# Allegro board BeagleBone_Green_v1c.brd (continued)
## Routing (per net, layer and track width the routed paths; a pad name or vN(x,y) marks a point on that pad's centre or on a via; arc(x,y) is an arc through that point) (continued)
GND_EARTH: length 298
  TOP w0.889: MTG1.1 16.37,4.94 ; MTG1.1 16.37,1.41 ; MTG1.1 12.84,4.94 ; MTG1.1 12.84,1.41 ; MTG4.1 82.41,50.03 ; MTG4.1 78.88,50.03 ; MTG4.1 82.41,46.49 ; MTG4.1 78.88,46.49 ; 12.84,53.2 MTG3.1 ; MTG3.1 16.37,49.67 ; MTG3.1 16.37,53.2 ; MTG2.1 82.41,4.58 ; MTG2.1 78.88,4.58 ; MTG2.1 78.88,8.12 ; MTG2.1 82.41,8.12 ; 0.84,48.06 P4.9 0.84,46.64 ; 0.84,41.62 P4.8 0.84,40.2
  LYR2_GND w0.889: 12.84,53.2 MTG3.1 ; MTG3.1 16.37,53.2 ; MTG3.1 16.37,49.67 ; 78.88,46.49 MTG4.1 ; MTG4.1 78.88,50.03 ; MTG4.1 82.41,46.49 ; MTG4.1 82.41,50.03 ; MTG2.1 82.41,8.12 ; MTG2.1 78.88,8.12 ; MTG2.1 82.41,4.58 ; MTG2.1 78.88,4.58 ; 0.84,41.62 P4.8 0.84,40.2 ; 12.84,1.41 MTG1.1 ; MTG1.1 16.37,4.94 ; MTG1.1 12.84,4.94 ; MTG1.1 16.37,1.41 ; 0.84,46.64 P4.9 0.84,48.06
  LYR3 w0.889: 12.84,53.2 MTG3.1 ; MTG3.1 16.37,49.67 ; MTG3.1 16.37,53.2 ; 78.88,46.49 MTG4.1 ; MTG4.1 82.41,50.03 ; MTG4.1 78.88,50.03 ; MTG4.1 82.41,46.49 ; 0.84,46.64 P4.9 0.84,48.06 ; 0.84,40.2 P4.8 0.84,41.62 ; MTG1.1 16.37,1.41 ; MTG1.1 12.84,1.41 ; MTG1.1 16.37,4.94 ; MTG1.1 12.84,4.94 ; MTG2.1 82.41,4.58 ; MTG2.1 82.41,8.12 ; MTG2.1 78.88,8.12 ; MTG2.1 78.88,4.58
  LYR4 w0.889: 0.84,41.62 P4.8 0.84,40.2 ; MTG3.1 16.37,53.2 ; MTG3.1 16.37,49.67 ; MTG3.1 12.84,53.2 ; 78.88,46.49 MTG4.1 ; MTG4.1 82.41,46.49 ; MTG4.1 78.88,50.03 ; MTG4.1 82.41,50.03 ; 78.88,4.58 MTG2.1 ; MTG2.1 78.88,8.12 ; MTG2.1 82.41,8.12 ; MTG2.1 82.41,4.58 ; 12.84,1.41 MTG1.1 ; MTG1.1 16.37,1.41 ; MTG1.1 16.37,4.94 ; MTG1.1 12.84,4.94 ; 0.84,46.64 P4.9 0.84,48.06
  LYR4 w1.016: 11.3,21.97 7.71,18.38 P3.5 ; P3.6 v1(7.57,2.33)
  LYR5_PWR w0.889: 12.84,4.94 MTG1.1 ; MTG1.1 12.84,1.41 ; MTG1.1 16.37,1.41 ; MTG1.1 16.37,4.94 ; 0.84,41.62 P4.8 0.84,40.2 ; 0.84,48.06 P4.9 0.84,46.64 ; MTG4.1 82.41,46.49 ; MTG4.1 78.88,46.49 ; MTG4.1 78.88,50.03 ; MTG4.1 82.41,50.03 ; 12.84,53.2 MTG3.1 ; MTG3.1 16.37,49.67 ; MTG3.1 16.37,53.2 ; 78.88,8.12 MTG2.1 ; MTG2.1 82.41,4.58 ; MTG2.1 78.88,4.58 ; MTG2.1 82.41,8.12
  BOTTOM w0.381: P10.13 v1(84.96,43.94) ; v1(78.23,45.59) 77.61,44.97 P10.11 ; P4.7 4.55,39.3 ; 4.55,39.3 v1(3.89,38.63) ; 4.55,39.3 v1(5.24,38.61) ; 71.07,39.95 71.11,39.99 P10.15 72.34,41.14 72.36,41.17 ; v1(1.91,30.23) 2.86,30.23 R136.2 2.86,29.46 v1(1.91,29.46) ; P4.6 4.55,48.69 ; P10.14 v1(84.96,31.55) ; 9.4,26.29 9.02,26.67 C164.2 ; C166.2 7.87,26.42 ; 71.97,35.14 P10.16 ; P10.12 76.44,30.47
  BOTTOM w0.508: C165.2 C163.2 8.64,32.26 10.67,34.29 10.67,37.08 P5.13 ; 6.03,38.42 6.1,38.48
  BOTTOM w0.889: 74.05,30.47 P10.12 ; P10.12 75.26,29.82 ; P10.12 75.26,31.12 ; P4.9 2.77,46.64 ; P4.9 0.84,46.64 ; P4.9 0.84,48.06 ; 0.84,40.2 P4.8 ; P4.8 2.77,40.2 ; P4.8 0.84,41.62 ; P4.8 2.77,41.62 ; 78.88,8.12 MTG2.1 ; MTG2.1 82.41,8.12 ; MTG2.1 82.41,4.58 ; MTG2.1 78.88,4.58 ; MTG3.1 16.37,49.67 ; MTG3.1 12.84,53.2 ; MTG3.1 16.37,53.2 ; MTG1.1 16.37,1.41 ; MTG1.1 12.84,1.41 ; MTG1.1 16.37,4.94 ; MTG1.1 12.84,4.94 ; 73.96,44.32 P10.11 72.75,44.97 ; 78.88,46.49 MTG4.1 ; MTG4.1 82.41,46.49 ; MTG4.1 78.88,50.03 ; MTG4.1 82.41,50.03
  vias: v1(1.19,45.62) v1(1.45,49.99) v1(84.91,36.91) v1(84.89,32.18) v1(84.99,40.13)
GND_OSC0: length 9.4
  TOP w0.381: v2(44.2,39.62) 44.52,39.3 U5.V11
  BOTTOM w0.305: U17.4 48.09,40.04 48.13,40.01 ; R29.2 52.45,44.32 ; R29.2 51.05,44.32 ; R29.2 C25.2 ; R173.2 44.07,43.31
  BOTTOM w0.381: R174.2 43.05,38.99 ; R173.2 43.31,42.42
GND_OSC1: length 7.3
  TOP w0.254: U5.A5 49.32,22.18 50.04,21.46
  BOTTOM w0.381: v1(51.75,14.86) C22.1 ; C22.1 R30.2 ; C22.1 51.12,15.68 ; v1(49.91,14.99) 50.48,15.56 C21.1 51.12,15.68 ; 51.12,15.68 v1(51.12,17.78)
GNDA_ADC: length 46.4
  TOP w0.254: v1(47.32,25.21) U5.E8
  TOP w0.305: 46.12,21.97 U5.A9
  TOP w0.381: 46.12,21.97 46.12,21.95 46.48,21.59 46.48,17.91 45.85,17.27 C93.2 ; C93.2 v1(45.09,16.51) ; C93.2 C33.2 C31.2 C32.2
  LYR4 w0.381: v1(47.32,25.21) 46.29,25.21 45.85,24.77 45.85,23.24 46.48,22.61 46.48,20.32 45.09,18.92 v1(45.09,16.51) 45.18,16.51 47.83,13.86 47.83,11.1 49.76,9.17 51.23,9.17 51.56,8.84 53.01,8.84 53.95,7.9 53.95,7.39 56.52,4.82 56.52,4.19 57.34,3.37 59.25,3.37 P9.34
  BOTTOM w0.381: v1(45.09,16.51) 45.09,16.89 44.84,17.14 FB3.1
VBUS: length 4.9
  BOTTOM w0.629: P3.1 11.15,16.18 ; P3.1 9.42,16.18 ; P3.1 11.15,14.45 ; P3.1 9.42,14.45
VDD_1V8: length 35.5
  TOP w0.203: U2.40 23.86,18.83 23.82,18.87 23.82,19.36 24.27,19.81
  TOP w0.254: U5.E9 U5.D10 v1(44.92,25.21) ; v1(40.12,32.41) U5.N16 ; U5.R16 40.14,33.99 v1(40.08,33.99)
  TOP w0.381: 24.27,19.81 25.46,19.81 v1(26.92,18.35) v1(26.92,17.72)
  LYR3 w0.381: v1(26.92,17.72) v1(26.92,18.35)
  BOTTOM w0.305: v1(44.92,25.21) 45.61,24.52 C88.1 ; v1(40.08,33.99) 39.76,34.31 39.76,34.37 39.32,34.81 39.12,34.81 38.69,35.24 C86.1
  BOTTOM w0.381: C14.2 26.04,17.72 v1(26.92,17.72) v1(26.92,18.35) 26.04,18.35 C14.2 ; C14.2 25.4,18.35 25.4,19.43 24.51,20.32 20.07,20.32 18.54,18.8 17.4,18.8 ; FB1.1 33.78,32.13 33.02,32.89 v1(33.02,33.27) 33.4,33.27 C78.1 33.53,33.91 v1(33.02,33.91) ; v1(45.88,14.06) 45.1,14.06 v1(45.06,14.1) 45.06,14.12 45.09,14.15 45.09,14.99 45.34,15.24 FB2.2 46.35,14.44 45.97,14.06 v1(45.88,14.06)
VDD_3V3A: length 117.8
  TOP w0.203: v1(22.36,19.62) 22.36,19.11 22.66,18.81 U2.43
  TOP w0.254: U5.K14 v1(42.52,30.01) U5.L14 ; v1(40.91,34.02) U5.R15 ; U5.P8 U5.P7 v1(48.12,33.21) ; U5.N5 v1(49.72,31.61) ; U5.E13 v1(43.32,25.21) U5.E12 v1(44.12,25.21) U5.E11 v1(44.92,26.01) U5.E10 ; U5.J14 v1(41.72,28.41) U5.H14 ; U5.P10 v1(44.92,33.21) U5.P11 ; U5.P13 v1(42.52,33.21) ; U5.F14 v1(41.72,26.81) U5.G14 ; U5.P6 v1(48.92,33.21) ; v1(40.92,32.41) U5.N15 ; U5.P5 v1(49.72,33.21) ; U5.P12 v1(43.32,33.21)
  TOP w0.381: U3.5 39.67,45.75 v1(39.69,45.73) ; v1(53.09,45.85) R56.1 ; v1(22.66,40.08) 22.66,40.59 22.35,40.89 R169.2 ; v1(26.99,23.11) R4.1 ; R4.1 R3.1 ; R4.1 C37.1 ; C61.2 75.06,46.23 v1(75.56,45.72) ; R1.1 23.62,20.57 v1(24.38,21.34) ; v1(37.34,40.53) 37.49,40.53 37.72,40.77 C159.1 38.61,40.77 38.93,40.45 Y4.4 ; v1(55.6,46.61) C57.2
  LYR3 w0.381: v1(22.66,40.08) 22.66,39.85 23.19,39.32 34.57,39.32 35.36,38.53 v1(36.12,38.53) ; v1(22.36,19.62) 22.36,19.44 21.34,18.41 17.02,18.41 16.51,17.91 16.51,16.08 15.29,14.86 11.81,14.86 10.92,13.97 9.4,13.97 9.14,13.72 5.59,13.72 3.05,16.26 2.26,16.26 v1(1.7,16.81)
  BOTTOM w0.305: U17.8 45.73,42.15 45.47,42.42 R175.1 v2(45.09,43.31) ; v1(41.72,28.41) 41.72,27.72 C60.2 41.72,27.5 v1(41.72,26.81) 41.72,26.12 C70.2 ; C72.2 45.43,25.5 v1(44.92,26.01) ; v1(42.52,30.01) 42.63,30.12 C66.1 ; v1(44.92,33.21) 45.61,33.9 C56.2 ; v1(40.92,32.41) 39.92,31.41 39.81,31.41 39.14,30.73 C87.1
  BOTTOM w0.381: v1(22.66,40.08) 22.58,40.16 21.08,40.16 20.7,40.54 U4.1 ; R57.1 59.82,46.28 v1(60.27,45.82) 60.71,46.25 R58.1 ; C71.2 37.85,36.96 v1(37.97,36.83) ; v1(68.38,45.8) R66.1 R67.1 R68.1 R69.1 C61.2 R70.1 75.95,46.1 v1(75.56,45.72) ; R63.1 65.02,46.13 v1(64.62,45.72) 64.62,45.85 64.14,46.33 R62.1 ; C59.1 v1(43.5,20.95) ; C77.1 35.5,36.83 v1(36.08,36.83) ; C77.1 34.8,36.77 C67.1 ; C77.1 35.18,37.87 35.84,38.53 v1(36.12,38.53) ; v1(53.09,45.85) R56.1 R55.1 ; R171.1 49.4,39.88 49.19,40.09 49.15,40.09 48.98,40.26 v2(48.77,40.26) ; v1(49.72,31.61) 49.83,31.72 C73.2 ; R172.1 43.81,40.39 43.43,40.77 43.43,40.85 v2(43.35,40.94) ; R61.1 62.87,46.25 v1(62.46,45.85) 61.98,46.33 R60.1 ; R14.1 29.97,12.06 v1(30.23,12.32) ; 26.99,21.4 C152.1 R156.1 ; 26.99,21.4 27.43,20.95 U7.4 ; 26.99,21.4 v1(26.99,23.11) ; R65.1 67.18,46.28 v1(66.75,45.85) 66.29,46.3 R64.1 ; C38.1 C67.1 ; C67.1 v1(35.56,35.56) ; R52.1 2.26,16.26 v1(1.7,16.81) ; v1(22.36,19.62) 22.36,19.31 21.97,18.92 C15.2 ; v1(39.69,45.73) C158.1 ; R59.1 v1(55.6,46.61)
VDD_3V3AUX: length 19.4
  TOP w0.203: U2.1 19.58,17.44 19.2,17.82
  TOP w0.381: 19.2,17.82 19.2,19.81 19.3,19.91 C18.1 19.3,20.7 18.54,21.46 13.59,21.46 12.38,20.25 10.73,20.25 10.46,20.52 D1.2
VDD_3V3B: length 131.4
  TOP w0.203: U13.C6 31.71,42.66 31.6,42.55 v1(31.6,42.55) 31.2,42.55 U13.E6 ; U13.P5 25.37,43.16 v1(25.32,43.21) ; v1(28.06,40.82) 28.06,40.82 28.07,40.83 28.07,40.92 28.31,41.16 U13.K9 ; U13.J10 29.09,40.4 28.93,40.23 28.93,40.09 v1(28.92,40.08) ; v1(30.35,43.69) 30.6,43.45 U13.F5 ; v1(25.98,44.16) U13.P3 U13.N4 ; U13.M4 v1(28.07,43.66)
  TOP w0.254: v1(28.45,30.87) 28,30.87 U14.12
  TOP w0.381: C29.1 v1(34.29,9.84) 34.86,10.41 36.83,10.41 37.47,11.05 37.47,12.64 37.21,12.89 R23.1 36.83,14.1 ; R119.1 v1(31.75,33.66)
  TOP w0.635: J5.3 74.91,32.4 v2(74.24,33.07) ; J4.3 v2(78.55,17.54)
  LYR3 w0.381: v1(34.29,9.84) 39.43,9.84 39.62,9.66 41.05,9.66 41.45,10.06 46.2,10.06 46.91,9.35 55.07,9.35 55.37,9.65 v1(55.37,10.16)
  LYR4 w0.381: v1(55.37,10.16) 55.37,12.06 54.36,13.08 v1(54.36,14.24)
  LYR4 w0.635: v2(78.55,17.54) 78.55,24.76 v2(77.29,26.01) 74.24,29.06 v2(74.24,33.07) 74.24,38.43 v2(75.34,39.52)
  LYR5_PWR w0.889: 22.96,2.64 P9.3 21.49,2.64 ; 21.49,5.18 P9.4 ; P9.4 22.96,5.18 ; P9.4 22.96,3.71 ; P9.4 21.49,3.71
  BOTTOM w0.191: v1(28.45,30.87) 28.86,31.27 30.86,31.27 30.99,31.15 R112.2
  BOTTOM w0.254: v1(30.35,43.69) 30.55,43.49 30.55,43.13 30.48,43.06 C129.1 30.87,42.42 31.01,42.55 v1(31.6,42.55) ; U15.7 55.11,11.18 C155.2 55.13,10.68 U15.8 ; v1(28.06,40.82) 28.07,40.82 28.07,40.91 28.32,41.16 28.57,41.16 28.82,41.4 C128.1 29.21,40.76 29.09,40.64 29.09,40.4 28.93,40.23 28.93,40.09 v1(28.92,40.08) ; v1(25.32,43.21) 25.4,43.13 C127.1 ; C130.1 33.76,42.42 v1(33.71,42.47)
  BOTTOM w0.381: R106.1 v1(43.81,45.72) ; R11.1 18.16,38.1 18.54,38.48 v1(18.54,38.61) 18.54,38.73 18.92,39.12 C20.1 19.18,39.75 18.16,40.77 U4.3 ; R114.2 R112.2 ; R103.1 v1(26.04,45.72) ; R163.1 47.94,14.54 48.26,14.22 54.34,14.22 v1(54.36,14.24) ; R102.1 v1(46.35,45.72) ; v1(83.88,41.47) 83.7,41.65 P10.4 ; v1(28.45,30.87) 26.16,33.15 C135.1 ; R101.1 v1(48.9,45.72) ; R108.1 v1(24.77,45.72) ; R119.1 v1(31.75,33.66) ; C155.2 v1(55.37,10.16) ; R109.1 v1(42.55,45.72) ; P2.5 v1(34.29,9.84) ; R105.1 v1(47.62,45.72) ; R152.1 R153.1 R154.1 78.23,26.92 77.9,26.59 77.88,26.59 v2(77.29,26.01) ; R107.1 v1(23.5,45.72) ; R110.1 v1(45.09,45.72) ; R111.1 v1(29.21,48.26) ; C126.2 v1(23.5,43.94) ; R104.1 v1(27.3,45.72) ; v1(70.76,42.16) R157.2
  BOTTOM w0.762: P9.3 P9.4
  vias: v1(25.72,35.88) v1(79.5,40.89)
VDD_5V: length 7.1
  TOP w0.203: U2.10 18.92,13.84
  LYR4 w0.889: 24.03,5.18 P9.6 ; P9.6 25.5,3.71 ; P9.6 24.03,3.71 ; P9.6 25.5,5.18 ; 25.5,2.64 P9.5 24.03,2.64
  vias: v1(18.03,13.08) v1(18.03,12.37)
VDD_ADC: length 33.1
  TOP w0.254: v1(47.32,24.41) U5.D8
  TOP w0.381: v1(45.85,18.41) 45.72,18.29 C93.1 45.09,19.34 R27.1 45.84,20.09 45.84,20.95 v1(45.85,20.95)
  LYR3 w0.381: v1(47.32,24.41) 46.71,25.02 46.23,25.02 45.85,24.64 v1(45.85,20.95)
  LYR4 w0.381: v1(45.85,18.41) 45.85,17.17 48.39,14.63 48.39,11.3 49.96,9.73 53.09,9.73 54.08,8.74 55.65,8.74 57.15,7.24 57.15,5.08 P9.32
  BOTTOM w0.381: v1(45.85,18.41) 45.85,17.65 46.35,17.14 FB2.1
VDD_CORE: length 46.3
  TOP w0.254: U5.F6 v1(48.92,26.81) U5.G6 ; U5.F7 v1(48.12,26.01) ; U5.M13 v1(42.52,31.61) ; U5.K12 v1(44.12,30.01) ; v1(47.32,30.81) U5.L8 ; v1(46.52,30.81) U5.L9 ; U5.K8 v1(47.32,30.01) U5.L7 ; U5.L6 v1(48.92,30.01) U5.K6 ; U5.M11 v1(44.92,30.81) ; U5.H11 v1(44.12,27.61) ; U5.N13 v1(43.32,31.61) U5.N12 ; U5.J12 v1(43.32,28.41) ; U5.N8 v1(46.52,32.41) U5.N9 ; v1(48.12,26.81) U5.G7 ; U5.G10 v1(44.92,27.61)
  LYR4 w0.508: v1(28.57,13.08) v1(29.21,13.08) 31.11,14.99 31.11,18.8 30.73,19.18 30.73,22.17 32.13,23.57 v1(32.13,24.77) v1(32.13,25.4)
  BOTTOM w0.305: v1(46.52,30.81) 45.83,30.81 C47.1 45.61,30.81 v1(44.92,30.81) ; C45.1 38.86,29.84 39.83,30.81 v1(40.12,30.81) ; v1(44.12,30.01) 43.61,29.5 C46.1 43.61,28.7 v1(43.32,28.41) v1(44.12,27.61) ; C50.1 47.43,26.01 v1(48.12,26.01) v1(48.12,26.81) v1(48.92,26.81) ; v1(44.92,27.61) 45.03,27.5 C49.1 ; v1(46.52,32.41) 46.12,32.81 45.83,32.81 C42.1 ; v1(43.32,31.61) v1(42.52,31.61) 42.52,32.3 C41.1 ; v1(48.92,30.01) v1(47.32,30.01) U5.K8 46.92,29.32 C48.1 ; C43.1 v1(47.32,30.81)
  BOTTOM w0.381: v1(39.32,26.81) C54.1 C44.1 ; 28.57,13.78 L3.2 29.21,13.78 v1(29.21,13.08) v1(28.57,13.08) 28.57,13.78
  vias: v1(35.56,27.37) v1(35.56,26.61)
VDD_MPU: length 28.7
  TOP w0.254: U5.F10 45.25,26.48 44.59,26.48 U5.F11 U5.F12 v1(43.32,26.01) U5.F13 v1(42.52,26.81) U5.G13 42.81,27.32 42.81,27.9 U5.H13 v1(42.52,28.41) U5.J13
  TOP w0.635: 35.41,21.56 34.92,21.08 34.92,19.56 33.15,17.78 33.15,13.97 30.48,11.3 26.29,11.3
  BOTTOM w0.305: v1(43.32,26.01) 43.43,25.9 C63.1
  BOTTOM w0.381: v1(42.52,28.41) 42.63,28.52 C65.1 ; C62.2 35.18,21.84 35.43,22.1 v1(36.08,22.1) v1(36.08,21.46) 35.31,21.46 C62.2 ; C62.2 34.8,21.21 C64.1
  vias: v1(26.48,9.91) v1(27.11,9.91)
VDD_MPUON: length 10.6
  TOP w0.121: U5.A2 51.72,20.67 52.32,20.07 52.32,19.3 52.7,18.92 53.21,18.92 54.48,17.65 54.48,16.76 54.99,16.26 55.57,16.26 56.27,15.56 TP2.1
VDD_PHYA: length 6.9
  TOP w0.254: U14.27 22,31.87 21.78,32.08 21.78,32.26 21.27,32.77 v1(21.27,33.02) ; U14.1 23.33,28.28 v1(22.91,27.86)
  BOTTOM w0.381: R122.2 v1(18.73,31.11) ; R120.2 v1(18.73,29.21) ; R121.2 v1(18.73,30.16) ; R137.2 v1(10.67,29.21) ; R123.2 v1(18.73,32.07)
VDD_PLL: length 12.9
  TOP w0.254: v1(44.12,33.21) U5.R11 v1(44.92,34.01) 45.32,33.62 U5.R10 ; v1(48.12,25.21) U5.E7 ; U5.H15 v1(40.92,27.61)
  LYR3 w0.381: v1(38.52,31.61) 39.08,31.05 39.51,31.05 39.85,31.39 39.85,31.62 40.11,31.88 41.14,31.88 41.22,31.96 41.23,31.96 41.66,32.38 43.29,32.38 v1(44.12,33.21) v1(44.92,34.01)
  BOTTOM w0.305: C94.1 v1(44.12,33.21)
  BOTTOM w0.635: FB1.2 37.92,31.61 v1(38.52,31.61)
VDD_RTC: length 5.4
  TOP w0.254: v1(48.92,24.41) U5.D6
  BOTTOM w0.121: C104.1 48.75,20.66 48.75,22.29 49.32,22.86 49.32,23.54 49.32,24.01 v1(48.92,24.41)
VDDS: length 45.9
  TOP w0.254: U5.E6 v1(48.92,25.21) ; v1(46.52,33.21) U5.P9 ; v1(46.52,26.01) U5.F9 ; v1(43.32,30.01) U5.K13 ; U5.E14 v1(41.72,25.21) ; v1(41.72,33.21) U5.P14 ; U5.N6 v1(48.12,31.61)
  LYR5_PWR w0.305: v1(45.72,29.21) 45.47,29.46 43.87,29.46 v1(43.32,30.01)
  BOTTOM w0.121: 41.32,35.26 41.32,33.61
  BOTTOM w0.254: 41.32,33.61 v1(41.72,33.21)
  BOTTOM w0.305: 41.32,35.26 41.45,35.4 41.45,36.17 C80.1
  BOTTOM w0.381: 39.24,22.73 39.24,21.84 38.88,21.48 37.83,21.48 36.32,22.99 33.02,22.99 32.12,23.89 21.22,23.89 16.99,19.66 16.66,19.66 16.38,19.38 R9.1 R8.2 ; C80.1 41.64,36.3 41.91,36.58 41.91,37.73 42.13,37.95 45.35,37.95 46.35,36.94 46.35,36.79 46.61,36.54 46.65,36.54 46.76,36.43 46.76,36.3
VDDS_DDR: length 54.9
  TOP w0.254: v1(67.1,25.57) U12.H9 ; U5.L5 v1(49.72,30.01) U5.K5 ; v1(60.7,30.37) U12.B2 ; v1(59.9,19.16) U12.R1 ; v1(59.9,27.17) U12.F1 ; v1(67.1,20.76) U12.N9 ; v1(59.9,20.76) U12.N1 ; U5.E5 U5.F5 v1(49.72,26.81) U5.G5 ; U5.H5 v1(49.72,28.41) U5.J5 ; v1(66.3,23.16) U12.K8 ; v1(60.7,23.16) U12.K2 ; v1(59.9,29.57) U12.C1 ; v1(67.1,29.57) U12.C9 ; v1(67.1,27.97) U12.E9 ; v1(67.1,19.16) U12.R9 ; v1(66.3,31.17) U12.A8 ; v1(65.5,26.37) U12.G7 ; v1(59.9,31.17) U12.A1 ; v1(61.5,27.97) U12.D2 ; v1(67.1,28.77) U12.D9
  TOP w0.305: v1(60.7,25.57) U12.H2
  TOP w0.381: v1(22.61,7.24) 22.61,8.26 C9.2 23.24,8.13 v1(23.24,7.24) ; C96.2 v1(55.37,15.81)
  BOTTOM w0.305: C100.1 49.72,26.12 v1(49.72,26.81) 49.72,27.5 C99.1 49.72,27.72 v1(49.72,28.41) 49.72,29.1 C98.1 49.72,29.32 v1(49.72,30.01) 49.72,30.7 C97.1
  BOTTOM w0.381: v1(55.37,15.81) 55.24,15.68 C103.1 C102.1 ; v1(59.9,29.57) C108.1 ; C116.1 67.29,28.57 v1(67.1,28.77) ; v1(67.1,29.57) C115.1 ; v1(66.3,23.16) 67.5,24.36 C119.1 ; v1(60.7,25.57) 60.18,26.09 60.13,26.09 60.12,26.09 59.68,26.09 59.15,25.57 C110.1 ; v1(52.83,20.32) 52.2,20.32 C101.1 ; v1(52.83,20.32) 53.59,20.32 C95.2 53.59,19.56 v1(52.83,19.56) v1(52.83,20.32) ; R97.1 v1(64.01,18.36) ; v1(67.1,25.57) C117.1 67.97,25.67 67.97,26.52 68.33,26.87 C118.2 67.44,27.05 67.1,27.39 v1(67.1,27.97) ; v1(59.9,20.76) C112.1 ; C107.1 v1(59.9,31.17) ; v1(67.1,20.76) C120.1 ; R98.1 64.7,25.57 v1(65.5,26.37) ; C113.1 v1(59.9,19.16) ; C109.1 v1(59.9,27.17) ; C111.1 59.49,22.61 60.14,22.61 v1(60.7,23.16) ; C114.1 v1(66.3,31.17) ; v1(67.1,19.16) C121.1 ; C122.2 v1(66.04,16.83)
  vias: v1(18.85,6.99) v1(19.86,7.09) v1(49.91,5.97) v1(50.55,5.97) v1(53.72,5.97) v1(54.36,5.97) v1(57.91,5.97) v1(58.67,5.97) v1(59.44,5.97)
AIN0: length 38.3
  TOP w0.121: P9.39 66.67,3.17 66.67,4.95 65.41,6.22 62.61,6.22 59.18,9.65 48.26,9.65 47.86,10.05 47.86,19.79 48.51,20.45 48.51,21.77 48.12,22.16 48.12,22.81 U5.B6
AIN1: length 32
  TOP w0.121: v1(48.12,23.61) U5.C7
  LYR4 w0.133: v1(48.12,23.61) 48.51,23.22 48.51,22.48 50.42,20.57 51.18,20.57 52.6,19.15 54.76,19.15 57.53,16.38 57.53,10.77 62.2,6.1 66.29,6.1 P9.40
AIN2: length 36.8
  TOP w0.121: P9.37 64.26,3.05 64.26,5.08 63.63,5.71 62.1,5.71 58.67,9.14 47.75,9.14 47.36,9.53 47.36,20.06 48.01,20.7 48.01,21.51 47.32,22.2 47.32,22.81 U5.B7
AIN3: length 33.1
  TOP w0.121: U5.A7 47.72,22.18 48.27,21.63 48.27,20.58 47.61,19.93 47.61,9.79 48.01,9.4 58.93,9.4 62.36,5.97 63.88,5.97 P9.38
AIN4: length 31.1
  TOP w0.121: U5.C8 v1(47.32,23.61)
  LYR4 w0.133: v1(47.32,23.61) 48.13,22.8 48.13,21.34 49.28,20.19 51.16,20.19 52.53,18.82 53.19,18.82 53.34,18.67 54.8,18.67 57.15,16.32 57.15,10.46 61.59,6.02 61.59,3.17 P9.33
AIN5: length 32.4
  TOP w0.121: U5.B8 46.52,22.81 46.52,22.19 46.86,21.84 46.86,9.02 47.24,8.64 58.24,8.64 62.43,4.45 P9.36
AIN6: length 35.8
  TOP w0.121: U5.A8 46.92,22.17 47.75,21.34 47.75,20.83 47.12,20.19 47.12,9.27 47.5,8.89 58.42,8.89 61.85,5.46 63.37,5.46 63.88,4.95 63.88,2.92 P9.35
AIN7: length 10.4
  TOP w0.121: U5.C9 v1(46.52,23.61)
  LYR4 w0.133: v1(46.52,23.61) 47.75,22.38 47.75,18.41 48.17,18 48.23,18 v1(48.26,17.97)
  BOTTOM w0.121: v1(48.26,17.97) 48.26,17.91 47.94,17.59 R163.2 48.39,16.7 48.58,16.51 48.58,15.88 48.77,15.68 R164.1
B_UART0_RX: length 13.6
  TOP w0.121: R165.1 46.35,7.24 47.12,6.48 49.02,6.48 J1.4
  BOTTOM w0.121: U15.2 51.94,11.18 52.2,10.92 52.2,9.65 J1.4
B_UART0_TX: length 5.2
  BOTTOM w0.121: J1.5 52.7,8.64 52.45,8.89 52.45,11.18 51.95,11.68 U15.3
CAP_VBB_MPU: length 4.2
  TOP w0.121: U5.C10 44.93,23.62 v1(44.92,23.61)
  BOTTOM w0.121: C91.1 45.4,22.42 44.92,22.9 v1(44.92,23.61)
CAP_VDD_SRAM_CORE: length 5.2
  TOP w0.121: U5.D9 v1(46.52,24.41)
  BOTTOM w0.121: v1(46.52,24.41) 46.92,24.01 46.92,23.04 46.35,22.48 C89.1
CAP_VDD_SRAM_MPU: length 5
  TOP w0.121: v1(44.12,24.41) U5.D11
  BOTTOM w0.121: C90.1 44.52,20.26 44.52,24.01 v1(44.12,24.41)
CLKOUT2: length 55.5
  BOTTOM w0.121: P2.18 36,17.46 35.67,17.8 35.67,19.98 36.28,20.59 39.9,20.59 40.13,20.83 40.89,20.83 41.08,20.64 41.08,19.68 R19.2 R20.1 42.55,18.54 41.59,17.59 41.59,14.95 42.89,13.65 46.7,13.65 46.89,13.84 60,13.84 67.36,6.48 69.98,6.48 71.63,4.83 71.63,3.05 P9.41
CLKOUT_SRC: length 5.1
  TOP w0.121: U5.D14 v1(41.72,24.41)
  BOTTOM w0.121: R19.1 41.59,22.99 41.32,23.26 41.32,24.01 v1(41.72,24.41)
CRS: length 2.7
  TOP w0.121: U14.14 28.55,31.87 28.92,32.24 29.51,32.24 R139.2
DDR_A0: length 23.9
  TOP w0.121: v1(61.5,20.76) U12.N3 ; U5.F3 v1(51.32,26.01)
  LYR3 w0.133: v1(53.85,23.11) 53.34,23.11 53.21,22.99 53.21,21.21 54.86,19.56 54.86,19.3 57.02,17.14 61.59,17.14 62.36,17.91 62.36,20.7 61.98,21.08 61.82,21.08 v1(61.5,20.76)
  BOTTOM w0.121: v1(51.32,26.01) 51.73,26.42 52.32,26.42 52.58,26.16 52.58,24.38 v1(53.85,23.11)
DDR_A1: length 24.1
  TOP w0.121: v1(58.93,23.88) 58.93,24.77 57.72,25.97 56.58,25.97 54.54,28.01 U5.H1 ; v1(65.5,19.96) U12.P7
  LYR3 w0.121: 60.2,23.87 60.5,23.57 61.67,23.57
  LYR3 w0.133: 61.67,23.57 61.78,23.57 62.23,23.11 62.61,23.11 63.88,21.84 63.88,20.83 63.5,20.45 63.5,18.9 63.63,18.77 64.39,18.77 64.52,18.9 64.52,19.05 64.39,19.18 64.01,19.18 63.88,19.3 63.88,20.19 64.01,20.32 64.14,20.32 64.26,20.19 64.26,19.68 64.39,19.56 64.64,19.56 64.77,19.68 64.77,20.19 64.9,20.32 65.14,20.32 v1(65.5,19.96) ; 60.2,23.87 58.93,23.87 v1(58.93,23.88)
DDR_A2: length 23.9
  TOP w0.121: v1(61.5,19.96) U12.P3 ; U5.E4 v1(50.52,25.21)
  LYR3 w0.121: v1(61.5,19.96) 61.1,20.36 61.1,22.09
  LYR3 w0.133: 61.1,22.09 60.83,22.35 59.44,22.35 59.05,21.97 56.77,21.97 56.64,22.1 56.64,23.5 56.77,23.62 57.4,23.62 57.51,23.72 57.51,24.16 57.4,24.26 56.77,24.26 56.64,24.38 56.64,25.4 54.72,27.32 54.5,27.32 54.26,27.08 54.26,26.9 55.12,26.04 55.12,25.15 54.36,24.38 51.12,24.38 50.52,24.98 v1(50.52,25.21)
DDR_A3: length 24
  TOP w0.121: v1(51.32,23.61) U5.C3 ; v1(60.7,20.76) U12.N2
  LYR3 w0.121: v1(60.7,20.76) 60.3,21.16 59.61,21.16
  LYR3 w0.133: v1(51.32,23.61) 52.2,23.61 52.32,23.48 52.32,22.35 52.45,22.23 52.7,22.23 52.83,22.35 52.83,23.48 52.96,23.61 55.04,23.61 55.12,23.53 55.12,23.32 55.04,23.24 54.37,23.24 54.29,23.16 54.29,22.94 54.37,22.86 55.04,22.86 55.12,22.78 55.12,22.56 55.04,22.48 54.37,22.48 54.29,22.4 54.29,22.2 54.37,22.12 54.53,22.12 54.61,22.05 54.61,21.67 54.69,21.59 54.91,21.59 54.99,21.67 54.99,22.05 55.07,22.12 55.42,22.12 55.5,22.2 55.5,24.43 55.58,24.51 55.8,24.51 55.88,24.43 55.88,21.34 56.01,21.21 59.56,21.21 59.61,21.16
DDR_A4: length 23.9
  TOP w0.121: v1(56.13,16.26) 56.52,16.64 56.52,17.02 53.72,19.81 53.72,20.57 52.96,21.34 52.96,22.53 52.68,22.81 52.36,22.81 52.12,23.05 52.12,23.61 U5.C2 ; v1(66.3,19.96) U12.P8
  LYR3 w0.121: 65.28,19.56 65.9,19.56 v1(66.3,19.96)
  LYR3 w0.133: v1(56.13,16.26) 56.39,16 62.36,16 63.12,16.76 64.77,16.76 65.02,17.02 65.02,19.3 65.28,19.56
DDR_A5: length 23.9
  TOP w0.121: U5.B1 52.74,23.21 53.34,22.61 53.34,22.23 53.47,22.1 v1(53.85,22.1) ; v1(60.7,19.96) U12.P2
  LYR3 w0.121: v1(60.7,19.96) 61.1,19.56 61.1,18.17 61.09,18.16
  LYR3 w0.133: 61.09,18.16 60.83,17.91 59.44,17.91 59.31,18.03 59.31,20.7 59.18,20.83 57.78,20.83 57.66,20.7 57.66,18.41 57.53,18.29 56.9,18.29 56.64,18.54 56.64,20.7 56.52,20.83 56.26,20.83 56.13,20.7 56.13,19.68 56.01,19.56 55.75,19.56 55.63,19.68 55.63,21.64 55.55,21.72 55.32,21.72 55.24,21.64 55.24,21.03 55.17,20.95 54.54,20.95 54.29,21.2 54.29,21.65 v1(53.85,22.1)
DDR_A6: length 24.1
  TOP w0.121: v1(66.3,19.16) U12.R8 ; v1(49.72,24.41) U5.D5
  BOTTOM w0.121: v1(49.72,24.41) 50.12,24.81 51.39,24.81 53.59,22.61 53.98,22.61 55.37,21.21 55.37,18.67 57.28,16.76 64.52,16.76 65.9,18.15 65.9,18.76 v1(66.3,19.16)
DDR_A7: length 24.1
  TOP w0.121: v1(60.7,19.16) U12.R2 ; v1(57.15,19.91) 57.63,19.43 58.17,19.43 58.29,19.3 58.29,18.03 58.17,17.91 57.4,17.91 55.63,19.68 55.63,23.88 54.36,25.15 54.36,25.78 54.13,26.01 52.12,26.01 U5.E2
  BOTTOM w0.121: v1(57.15,19.91) 59.16,19.91 59.61,20.36 62.23,20.36 62.36,20.24 62.36,19.69 62.23,19.56 U12.R2 v1(60.7,19.16)
DDR_A8: length 23.9
  TOP w0.121: v1(66.3,18.36) U12.T8 ; v1(50.52,24.41) U5.D4
  BOTTOM w0.121: v1(66.3,18.36) 66.3,18.04 64.64,16.38 57.15,16.38 54.99,18.54 54.99,20.68 54.61,21.06 52.19,21.06 51.94,21.31 51.94,23.75 51.28,24.41 v1(50.52,24.41)
DDR_A9: length 24
  TOP w0.121: v1(53.85,21.46) 53.85,20.95 53.97,20.83 54.13,20.83 54.25,20.95 54.25,22.46 54.1,22.61 53.79,22.61 53.09,23.31 53.09,23.44 U5.C1 ; v1(61.5,19.16) U12.R3
  LYR3 w0.133: v1(61.5,19.16) 61.5,19.43 61.63,19.56 61.85,19.56 61.98,19.43 61.98,18.03 61.47,17.53 58.93,17.53 58.8,17.65 58.8,20.32 58.67,20.45 58.29,20.45 58.17,20.32 58.17,17.65 58.04,17.53 57.15,17.53 55.24,19.43 55.24,20.32 54.99,20.57 54.36,20.57 53.85,21.08 v1(53.85,21.46)
DDR_A10: length 24
  TOP w0.121: v1(65.5,22.36) U12.L7 ; U5.F4 v1(50.52,26.01)
  LYR3 w0.121: 51.68,26.41 50.92,26.41 v1(50.52,26.01)
  LYR3 w0.133: 51.68,26.41 52.2,26.92 52.2,28.32 52.58,28.71 55.75,28.71 56.83,27.62 57.72,27.62 59.31,26.04 62.36,26.04 64.39,24 65.66,24 65.79,23.88 65.79,23.62 65.66,23.5 64.77,23.5 64.64,23.37 64.64,23.11 64.77,22.99 65.66,22.99 65.79,22.86 65.79,22.65 v1(65.5,22.36)
DDR_A11: length 23.9
  TOP w0.121: v1(65.5,19.16) U12.R7 ; v1(53.85,26.81) 52.12,26.81 U5.F2
  BOTTOM w0.121: v1(65.5,19.16) 65.02,19.16 64.77,18.91 64.77,18.16 64.14,17.53 57.53,17.53 56.13,18.92 56.13,23.24 55.88,23.5 54.61,23.5 53.34,24.77 53.34,26.3 v1(53.85,26.81)
DDR_A12: length 24.1
  TOP w0.121: v1(65.5,20.76) U12.N7 ; v1(51.32,25.21) U5.E3
  LYR3 w0.133: v1(51.32,25.21) 51.38,25.15 54.1,25.15 54.36,25.4 54.36,25.78 54.1,26.04 53.21,26.04 52.96,26.29 52.96,27.69 53.21,27.94 55.12,27.94 56.64,26.42 57.91,26.42 59.56,24.77 61.22,24.77 61.47,25.02 62.23,25.02 63.88,23.37 63.88,22.38 v1(65.5,20.76)
DDR_A13: length 24
  TOP w0.121: U5.H3 v1(51.32,27.61) ; v1(61.5,18.36) U12.T3
  BOTTOM w0.121: v1(51.32,27.61) 53.92,27.61 54.36,27.18 54.36,24.26 54.74,23.88 56.26,23.88 56.52,23.62 56.52,19.05 57.66,17.91 63.37,17.91 63.5,18.03 63.5,18.24 63.37,18.36 v1(61.5,18.36)
DDR_A14: length 24
  TOP w0.121: v1(50.52,27.61) U5.H4 ; v1(65.5,18.36) U12.T7
  BOTTOM w0.121: v1(50.52,27.61) 50.52,27.58 50.9,27.21 52.55,27.21 52.96,26.8 52.96,24.64 55.75,21.84 55.75,18.8 57.4,17.14 64.28,17.14 v1(65.5,18.36)
DDR_A15: length 24
  TOP w0.121: U12.M7 64.52,21.38 64.52,18.11 63.07,16.66 57.35,16.66 54.61,19.41 54.61,23.37 53.57,24.41 51.32,24.41 U5.D3
DDR_BA0: length 24.1
  TOP w0.121: v1(60.7,21.56) U12.M2 ; U5.C4 v1(50.52,23.61)
  LYR3 w0.121: 50.12,22.48 50.12,23.48 50.25,23.61 v1(50.52,23.61) ; 50.92,23.74 50.92,22.48
  LYR3 w0.133: 50.92,22.48 51.05,22.35 51.44,22.35 51.56,22.23 51.56,21.46 51.44,21.34 51.18,21.34 51.05,21.46 51.05,21.84 50.93,21.97 50.67,21.97 50.55,21.84 50.55,21.46 50.42,21.34 50.25,21.34 50.12,21.46 50.12,22.48 ; 50.92,23.74 50.92,23.89 51.05,24.02 54.5,24.02 55.5,25.02 55.5,25.65 55.6,25.75 55.78,25.75 56.26,25.27 56.26,21.97 56.64,21.59 59.18,21.59 59.56,21.97 60.57,21.97 60.7,21.84 v1(60.7,21.56)
DDR_BA1: length 24.1
  TOP w0.121: v1(66.3,20.76) U12.N8 ; U5.E1 v1(53.85,25.61)
  LYR3 w0.133: v1(53.85,25.61) 52.62,25.61 52.32,25.91 52.32,26.29 52.58,26.54 52.58,28.07 52.83,28.32 55.37,28.32 56.93,26.76 58.08,26.76 59.69,25.15 61.09,25.15 61.21,25.27 61.21,25.53 61.34,25.65 62.1,25.65 64.23,23.52 64.23,22.63 65.05,21.82 65.66,21.82 65.82,21.65 65.82,21.24 v1(66.3,20.76)
DDR_BA2: length 24.1
  TOP w0.121: v1(61.5,21.56) U12.M3 ; v1(51.32,22.81) U5.B3
  LYR3 w0.133: v1(61.5,21.56) 61.98,21.56 62.1,21.69 62.1,22.1 62.23,22.23 62.48,22.23 62.74,21.97 62.74,21.59 62.48,21.34 62.48,21.08 62.74,20.83 62.74,17.53 61.98,16.76 56.9,16.76 54.48,19.18 54.48,19.43 52.7,21.21 52.51,21.21 52.39,21.08 52.39,20.83 52.26,20.7 52.07,20.7 51.94,20.83 51.94,22.99 51.82,23.11 51.63,23.11 v1(51.32,22.81)
DDR_CASN: length 24
  TOP w0.121: U5.F1 54.48,26.41 54.74,26.16 54.74,25.4 55.37,24.77 55.88,24.77 56.01,24.64 56.01,19.81 56.13,19.68 56.52,19.68 56.64,19.81 56.64,21.21 56.77,21.34 57.42,21.34 57.55,21.21 57.55,19.94 57.68,19.81 58.17,19.81 58.29,19.94 58.29,20.19 58.17,20.32 58.04,20.32 57.91,20.45 57.91,20.7 58.04,20.83 58.17,20.83 58.29,20.95 58.29,21.46 58.17,21.59 57.28,21.59 57.15,21.72 v1(57.15,22.48) ; v1(61.5,23.16) U12.K3
  LYR3 w0.133: v1(57.15,22.48) 59.05,22.48 59.31,22.73 61.07,22.73 v1(61.5,23.16)
DDR_CKE: length 25.1
  TOP w0.121: v1(67.1,23.16) U12.K9 ; U5.G3 v1(51.32,26.81)
  LYR3 w0.133: v1(51.32,26.81) 51.82,27.3 51.82,28.83 51.69,28.96 51.18,28.96 51.05,29.08 51.05,29.34 51.18,29.46 52.83,29.46 53.21,29.08 55.88,29.08 57.02,27.94 57.91,27.94 59.44,26.42 62.61,26.42 64.64,24.38 67.18,24.38 67.31,24.26 67.31,23.37 v1(67.1,23.16)
  BOTTOM w0.121: R96.2 v1(67.1,23.16)
DDR_CLK: length 24
  TOP w0.095: U12.J7 64.94,24.2 64.74,24.2 63.75,23.22 63.75,19.7 61.58,17.53 57.42,17.53 55.27,19.67 55.27,23.72 53.8,25.2 52.36,25.2 51.98,24.81 U5.D2
DDR_CLKN: length 24
  TOP w0.095: U12.K7 65.37,23.56 65.48,23.67 65.48,23.82 65.37,23.92 64.85,23.92 64.03,23.1 64.03,19.58 61.7,17.25 57.3,17.25 54.99,19.56 54.99,23.61 53.68,24.92 52.63,24.92 U5.D1
DDR_CSN: length 23.9
  TOP w0.121: U5.H2 52.12,28.41 54.65,28.41 56.71,26.35 57.85,26.35 59.44,24.77 59.44,23.44 59.36,23.37 58.88,23.37 58.8,23.29 58.8,22.09 59.05,21.84 59.05,18.41 59.18,18.29 59.31,18.29 59.44,18.41 59.44,21.97 59.18,22.23 59.18,22.78 59.26,22.86 59.49,22.86 59.56,22.78 59.56,22.44 59.64,22.36 60.7,22.36 U12.L2
DDR_D0: length 23.3
  TOP w0.121: v1(51.32,31.61) U5.M3 ; v1(62.3,27.97) U12.E3
  LYR3 w0.133: v1(51.32,31.61) 51.68,31.61 52.96,32.89 60.45,32.89 63.75,29.59 63.75,27.43 63.63,27.3 63.12,27.3 62.99,27.43 62.99,29.72 62.87,29.84 62.43,29.84 62.3,29.72 v1(62.3,27.97)
DDR_D1: length 23.3
  TOP w0.121: v1(65.5,27.17) U12.F7 ; v1(50.52,31.61) U5.M4
  LYR3 w0.121: v1(65.5,27.17) 65.9,26.77 66.47,26.77 66.7,26.53 66.7,25.74 66.7,25.39 66.47,25.16 ; v1(50.52,31.61) 50.92,31.21 50.92,30.64 51.16,30.41 52.78,30.41
  LYR3 w0.133: 66.47,25.16 66.08,24.77 64.89,24.77 62.9,26.76 59.6,26.76 57.4,28.96 56.77,28.96 56.26,29.46 53.72,29.46 52.78,30.41
DDR_D2: length 23.3
  TOP w0.121: U5.N1 55.49,32.01 55.88,31.62 57.02,31.62 57.15,31.75 57.15,32.64 57.02,32.77 54.86,32.77 54.74,32.89 54.74,33.15 54.86,33.27 61.09,33.27 61.21,33.15 61.21,32.13 62.73,30.61 62.73,27.43 62.47,27.17 61.98,27.17 61.98,27.17 61.5,27.17 U12.F2
DDR_D3: length 23.3
  TOP w0.121: U5.N2 52.12,32.41 55.86,32.41 v1(56.13,32.13) ; v1(66.3,27.17) U12.F8
  BOTTOM w0.121: v1(56.13,32.13) 60.83,32.13 62.36,30.61 62.36,29.08 63.18,28.26 63.18,27.69 63.31,27.56 63.5,27.56 63.63,27.69 63.63,28.57 63.75,28.7 64.01,28.7 64.14,28.57 64.14,27.69 64.26,27.56 64.52,27.56 64.64,27.69 64.64,28.57 64.77,28.7 65.58,28.7 65.91,28.37 66.5,28.37 66.7,28.17 66.7,27.57 v1(66.3,27.17)
DDR_D4: length 23.3
  TOP w0.121: U12.H3 63.52,25.17 64.26,25.91 64.26,31.75 63.37,32.64 v1(62.36,32.64) ; U5.N3 v1(51.32,32.41)
  LYR3 w0.133: v1(51.32,32.41) 51.33,32.41 52.58,33.66 61.34,33.66 v1(62.36,32.64)
DDR_D5: length 23.3
  TOP w0.121: U5.N4 v1(50.52,32.41) ; v1(66.3,25.57) U12.H8
  LYR3 w0.121: v1(50.52,32.41) 50.92,32.01 51.57,32.01
  LYR3 w0.133: v1(66.3,25.57) 65.88,25.15 65.15,25.15 64.26,26.04 64.26,29.72 60.71,33.27 52.83,33.27 51.57,32.01
DDR_D6: length 23.3
  TOP w0.121: U12.G2 61.5,25.56 63.41,25.56 63.88,26.04 63.88,31.24 v1(62.99,32.13) ; U5.P3 v1(51.32,33.21)
  LYR3 w0.133: v1(62.99,32.13) 62.99,32.64 61.59,34.04 52.45,34.04 51.63,33.21 v1(51.32,33.21)
DDR_D7: length 23.3
  TOP w0.121: v1(65.5,25.57) U12.H7 ; U5.P4 v1(50.52,33.21)
  LYR3 w0.121: 51.62,33.61 50.92,33.61 v1(50.52,33.21)
  LYR3 w0.133: 51.62,33.61 52.4,34.39 61.87,34.39 64.77,31.5 64.77,26.3 v1(65.5,25.57)
DDR_D8: length 20.3
  TOP w0.121: U5.J1 54.76,28.81 56.83,26.73 58.86,26.73 59.37,26.23 59.37,25.34 59.94,24.77 62.23,24.77 62.36,24.64 62.36,23.24 62.48,23.11 62.99,23.11 64.64,24.77 64.64,27.91 U12.D7
DDR_D9: length 20.3
  TOP w0.121: U5.K1 55.77,29.61 v1(56.13,29.97) ; v1(61.5,29.57) U12.C3
  LYR3 w0.133: v1(56.13,29.97) 56.52,29.97 56.64,30.1 56.64,32 56.77,32.13 57.53,32.13 57.66,32 57.66,29.84 57.78,29.72 58.29,29.72 58.42,29.84 58.42,32 58.55,32.13 59.05,32.13 59.18,32 59.18,28.83 59.31,28.7 61.37,28.7 61.5,28.83 v1(61.5,29.57)
DDR_D10: length 20.3
  TOP w0.121: v1(66.3,29.57) U12.C8 ; U5.K2 52.12,30.01 v1(53.85,30.01)
  BOTTOM w0.121: v1(66.3,29.57) 65.82,29.08 62.99,29.08 62.74,29.34 62.74,30.73 60.83,32.64 55.75,32.64 55.24,32.13 55.24,29.97 55.12,29.84 54.48,29.84 54.32,30.01 v1(53.85,30.01)
DDR_D11: length 20.1
  TOP w0.121: v1(60.7,29.57) U12.C2 ; v1(51.32,30.01) U5.K3
  BOTTOM w0.121: v1(60.7,29.57) 61,29.27 61,29.08 60.88,28.96 58.17,28.96 58.04,28.83 58.04,28.57 58.17,28.45 60.12,28.45 60.24,28.33 60.24,27.93 60.07,27.76 57.81,27.76 57.56,28.02 57.56,28.84 57.44,28.96 55.75,28.96 55.24,29.46 53.59,29.46 53.42,29.64 53.42,30.21 53.3,30.33 53.06,30.33 52.96,30.23 52.96,29.59 52.83,29.46 51.22,29.46 51.1,29.58 51.1,29.79 v1(51.32,30.01)
DDR_D12: length 20.2
  TOP w0.121: v1(65.5,31.17) U12.A7 ; U5.K4 v1(50.52,30.01)
  BOTTOM w0.121: v1(65.5,31.17) 65.5,31.53 63.31,33.72 54.55,33.72 52.58,31.75 52.58,30.16 52.45,30.04 52.2,30.04 52.07,30.16 52.07,30.28 51.94,30.41 50.92,30.41 v1(50.52,30.01)
DDR_D13: length 20.2
  TOP w0.121: v1(60.7,31.17) U12.A2 ; v1(51.32,30.81) U5.L3
  LYR3 w0.133: v1(60.7,31.17) 60.71,31.17 60.71,32 60.17,32.54 53.21,32.54 53.09,32.41 53.09,32 53.21,31.88 55.5,31.88 55.63,31.75 55.63,30.1 55.5,29.97 54.48,29.97 54.36,30.1 54.36,31.11 54.23,31.24 52.07,31.24 51.64,30.81 v1(51.32,30.81)
DDR_D14: length 20.3
  TOP w0.121: v1(66.3,30.37) U12.B8 ; U5.L4 v1(50.52,30.81)
  BOTTOM w0.121: v1(66.3,30.37) 65.9,30.77 65.9,31.64 63.5,34.04 54.36,34.04 51.53,31.21 50.92,31.21 v1(50.52,30.81)
DDR_D15: length 20.1
  TOP w0.121: U5.M1 53.34,31.21 54.86,31.21 54.99,31.08 54.99,30.86 54.86,30.73 54.48,30.73 54.36,30.61 54.36,30.23 54.48,30.1 55.5,30.1 55.63,30.23 55.63,30.48 55.75,30.61 59.31,30.61 59.44,30.73 59.44,30.99 59.31,31.11 58.04,31.11 57.91,31.24 57.91,31.5 58.04,31.62 59.31,31.62 59.44,31.75 59.44,32 59.31,32.13 58.04,32.13 57.91,32.26 57.91,32.51 58.04,32.64 60.03,32.64 U12.A3
DDR_DQM0: length 23.3
  TOP w0.121: v1(65.5,27.97) U12.E7 ; U5.M2 52.12,31.61 55.26,31.61 55.7,31.17 v1(56.13,31.17)
  BOTTOM w0.121: v1(65.5,27.97) 65.15,27.97 65.02,27.84 65.02,27.3 64.9,27.18 62.87,27.18 62.74,27.3 62.74,28.19 61.98,28.96 61.98,30.48 60.71,31.75 56.77,31.75 56.64,31.62 56.64,29.59 56.52,29.46 55.75,29.46 55.63,29.59 55.63,31.04 55.75,31.17 v1(56.13,31.17)
DDR_DQM1: length 20.2
  TOP w0.121: U12.D3 61.5,28.76 60.01,28.76 59.44,28.19 57.78,28.19 57.66,28.32 57.66,28.57 57.78,28.7 59.31,28.7 59.44,28.83 59.44,29.08 59.31,29.21 57.78,29.21 57.66,29.34 57.66,29.59 57.78,29.72 59.31,29.72 59.44,29.84 59.44,30.1 59.31,30.23 56.77,30.23 56.64,30.1 56.64,29.34 56.52,29.21 52.12,29.21 U5.J2
DDR_DQS0: length 23.3
  TOP w0.095: U5.P1 52.62,32.91 53.76,32.91 54.62,33.78 62.99,33.78 63.12,33.66 63.12,33.43 62.99,33.31 62.01,33.31 61.69,32.99 61.69,32.28 63.22,30.75 63.22,26.53 62.93,26.24 62.75,26.24 62.67,26.32 62.67,26.73 62.6,26.8 62.37,26.8 62.29,26.73 62.29,26.44 62.22,26.37 61.62,26.37 61.54,26.44 61.54,26.69 61.62,26.77 U12.F3
DDR_DQS1: length 20.3
  TOP w0.095: v1(53.85,30.81) 53.45,30.41 U5.L1
  TOP w0.121: v1(65.5,29.57) U12.C7
  BOTTOM w0.095: v1(65.5,29.57) 65.54,29.57 65.61,29.64 65.61,29.9 65.54,29.97 63.64,29.97 63.35,30.26 63.35,30.85 63.64,31.14 63.91,31.14 64.14,31.37 64.14,31.75 62.86,33.03 54.76,33.03 54.38,32.65 54.38,32.42 54.76,32.04 54.76,31.66 54.47,31.37 53.75,31.37 53.62,31.24 53.62,31.04 v1(53.85,30.81)
DDR_DQSN0: length 23.3
  TOP w0.095: U5.P2 52.1,33.19 53.64,33.19 54.51,34.06 63.11,34.06 63.4,33.77 63.4,33.32 63.11,33.03 62.12,33.03 61.97,32.87 61.97,32.39 63.5,30.86 63.5,26.42 63.05,25.97 U12.G3
DDR_DQSN1: length 20.3
  TOP w0.095: U5.L2 52.12,30.81 v1(53.09,30.81)
  TOP w0.121: v1(65.5,30.37) U12.B7
  BOTTOM w0.095: v1(65.5,30.37) 65.39,30.25 63.75,30.25 63.63,30.38 63.63,30.73 63.75,30.86 64.02,30.86 64.41,31.25 64.41,31.87 62.97,33.31 54.64,33.31 54.1,32.77 54.1,32.31 54.48,31.93 54.48,31.78 54.36,31.65 53.63,31.65 53.34,31.36 53.34,31.06 v1(53.09,30.81)
DDR_ODT: length 24.1
  TOP w0.121: v1(59.9,23.16) U12.K1 ; U5.G1 53.68,27.21 54.32,27.21 55.12,26.42 55.12,25.53 55.5,25.15 56.13,25.15 56.39,24.89 56.39,21.7 56.49,21.59 56.64,21.59 56.75,21.7 56.75,24.26 56.86,24.37 57.3,24.37 57.4,24.26 57.4,23.62 57.55,23.48 57.55,22.1 57.68,21.97 57.91,21.97 58.04,22.1 58.04,23.75 v1(57.91,23.88)
  LYR3 w0.133: v1(59.9,23.16) 59.23,23.16 58.93,22.86 58.04,22.86 57.91,22.99 57.91,23.24 58.04,23.37 58.29,23.37 58.42,23.5 58.42,24.89 58.17,25.15 57.78,25.15 57.66,25.02 57.66,24.64 57.91,24.38 v1(57.91,23.88)
DDR_RASN: length 24
  TOP w0.121: U5.G4 v1(50.52,26.81) ; v1(61.5,23.96) U12.J3
  LYR3 w0.121: 51.33,24.77 51.17,24.77 50.92,25.02 50.92,25.41 50.72,25.61 50.34,25.61 50.12,25.83 50.12,26.41 v1(50.52,26.81)
  LYR3 w0.133: 51.33,24.77 54.23,24.77 54.74,25.27 54.74,25.91 54.24,26.4 53.47,26.4 53.34,26.53 53.34,27.43 53.47,27.56 54.99,27.56 56.5,26.05 57.77,26.05 59.42,24.4 61.35,24.4 61.59,24.64 62.1,24.64 62.84,23.9 62.84,23.72 62.69,23.58 62.51,23.58 62.12,23.96 v1(61.5,23.96)
DDR_RESETN: length 20.7
  TOP w0.121: U5.G2 52.12,27.61 54.43,27.61 55.5,26.54 55.5,25.78 55.75,25.53 56.39,25.53 56.75,25.16 57.89,25.16 58.42,24.64 58.42,21.97 58.67,21.72 58.67,18.03 58.8,17.91 60.24,17.91 v1(60.7,18.36) U12.T2
  BOTTOM w0.121: R97.2 62.36,19.16 61.96,18.76 U12.T2 v1(60.7,18.36)
DDR_VREF: length 27.1
  TOP w0.305: v1(59.9,25.57) U12.H1 ; v1(66.3,21.56) U12.M8 ; v1(50.52,28.41) U5.J4
  BOTTOM w0.381: R98.2 C123.1 62.99,24 63.23,23.77 63.45,23.77 63.46,23.76 63.63,23.76 64.01,23.38 R100.1 C124.1 64.77,21.96 65.17,21.56 v1(66.3,21.56) ; R98.2 62.4,25.57 61.82,24.99 60.47,24.99 v1(59.9,25.57) ; R98.2 62.99,26.11 62.51,26.59 60.34,26.59 60.33,26.6 59.47,26.6 59.36,26.49 56.31,26.49 55.37,27.43 C28.1 55.03,28.41 54.48,28.96 51.07,28.96 v1(50.52,28.41)
DDR_VTP: length 6.7
  TOP w0.305: v1(51.32,28.41) U5.J3
  BOTTOM w0.381: R22.2 54.86,26.16 54.86,27.69 54.14,28.41 v1(51.32,28.41)
DDR_WEN: length 23.9
  TOP w0.121: v1(61.5,22.36) U12.L3 ; v1(55.37,17.53) 55.37,17.68 53.47,19.58 53.47,20.32 52.96,20.83 52.24,20.83 52.12,20.95 52.12,22.57 51.72,22.97 U5.B2
  LYR3 w0.133: v1(61.5,22.36) 61.87,22.73 62.48,22.73 63.5,21.72 63.5,20.95 63.12,20.57 63.12,17.27 62.23,16.38 56.77,16.38 55.63,17.52 55.38,17.52 v1(55.37,17.53)
EHRPWM1A: length 42.1
  TOP w0.121: U5.U14 42.52,35.61 42.52,38.1 41.63,38.99 41.02,38.99 v1(40.34,38.3)
  LYR4 w0.133: v1(40.34,38.3) 40.34,36.65 37.24,33.55 37.24,28.24 36.06,27.07 36.06,26.29 35.56,25.78 35.56,23.24 35.43,23.11 35.43,19.06 35.56,18.92 35.56,9.78 34.9,9.12 34.9,4.47 P9.14
EHRPWM1B: length 36.3
  TOP w0.121: v1(41.72,34.81) U5.T14
  LYR4 w0.133: P9.16 36.96,4.95 36.96,18.92 36.49,19.39 36.49,22.7 36.3,22.89 36.3,25.5 37.97,27.18 37.97,33.32 40.64,35.99 41.09,35.99 41.72,35.36 v1(41.72,34.81)
EHRPWM2A: length 16.8
  TOP w0.121: U5.U10 45.72,35.61 45.72,36.07 45.72,36.07 45.72,36.17 45.96,36.41 45.96,36.41 46.18,36.62 46.18,43.87 44.58,45.47 44.58,48.13 P8.19
EHRPWM2B: length 28.2
  TOP w0.121: v1(44.92,34.81) U5.T10
  LYR3 w0.133: P8.13 33.5,48.74 33.5,43.67 34.45,42.72 37.26,42.72 38.61,44.07 42.29,44.07 43.31,43.05 43.31,41.66 42.7,41.05 42.7,40.54 43.59,39.66 43.59,39.34 44.38,38.55 44.38,35.35 v1(44.92,34.81)
EMMC_RSTN: length 4.8
  TOP w0.203: U13.K5 v1(29.09,43.66)
  BOTTOM w0.121: R162.2 R111.2 29.21,44.57 29.09,44.45 v1(29.09,43.66)
EMMC_VCCI: length 2.5
  TOP w0.076: 31.87,45.35 31.85,45.32 31.85,44.91 U13.C2
  TOP w0.121: v1(32.61,45.82) 32.35,45.82 31.87,45.35
  BOTTOM w0.121: v1(32.61,45.82) 32.61,45.9 32.38,46.13 C125.1
ENZ_KALDO_1P8V: length 3.4
  TOP w0.121: U5.B4 v1(50.52,22.81)
  BOTTOM w0.121: v1(50.52,22.81) 51.12,22.21 R54.2
ETH_TXD4: length 4.4
  TOP w0.121: v1(29.21,34.61) 26.73,34.61 26.33,34.21 U14.18
  BOTTOM w0.121: R145.1 v1(29.21,34.61)
GPIO0_7: length 45.9
  TOP w0.121: v1(36.07,18.03) 36.32,18.29 R50.1
  BOTTOM w0.121: P9.42 68.9,6.03 67.45,6.03 59.89,13.59 46.99,13.59 46.81,13.4 42.75,13.4 41.27,14.88 41.27,17.91 40.64,18.54 R51.1 39.75,19.18 39.37,19.56 37.85,19.56 37.21,20.19 36.7,20.19 36.47,19.96 36.47,19.45 36.07,19.05 v1(36.07,18.03)
GPIO0_7SRC: length 9.2
  TOP w0.121: R50.2 36.07,17.27 35.61,17.73 35.61,19.99 37.08,21.46 37.08,22.48 38.62,24.01 U5.C18
GPIO0_26: length 30.5
  TOP w0.121: v1(44.12,34.81) U5.T11
  LYR3 w0.133: v1(44.12,34.81) 44.12,38.43 43.23,39.32 43.23,39.68 42.41,40.5 42.41,41.27 43.05,41.91 43.05,42.93 42.29,43.69 38.56,43.69 37.36,42.49 34.35,42.49 33.27,43.57 33.27,43.77 33.27,49.7 33.66,50.08 33.66,51.44 P8.14
GPIO0_27: length 18.3
  TOP w0.121: P8.17 40.01,49.78 40.46,49.33 41.53,49.33 41.83,49.02 42.67,49.02 43.31,48.39 43.31,45.37 44.2,44.48 44.2,40.39 43.72,39.91 43.72,37.11 44.12,36.71 44.12,35.61 U5.U12
GPIO1_12: length 30.2
  TOP w0.121: v1(43.32,34.81) U5.T12
  LYR3 w0.133: P8.12 31.43,51.75 31.43,44.54 32.26,43.71 32.26,43.01 33.44,41.83 33.97,41.83 34.15,42.01 37.72,42.01 38.89,43.18 41.15,43.18 41.89,42.44 41.89,40.36 42.49,39.75 42.49,38.96 43.32,38.14 v1(43.32,34.81)
GPIO1_13: length 28.5
  TOP w0.121: v1(43.32,34.01) U5.R12
  LYR3 w0.121: 43.76,38.28 43.76,35.02 43.72,34.98 43.72,34.65 43.76,34.6 43.76,34.46 v1(43.32,34.01)
  LYR3 w0.133: 43.76,38.28 42.98,39.07 42.98,39.6 42.16,40.42 42.16,42.55 41.27,43.43 38.73,43.43 37.54,42.24 34.05,42.24 33.87,42.06 33.54,42.06 32.69,42.91 32.69,43.79 31.98,44.5 31.98,49.76 P8.11
GPIO1_14: length 22.1
  TOP w0.121: U5.V13 42.92,36.35 42.92,38.61 42.55,38.99 42.55,41.4 43.05,41.91 43.05,44.07 41.78,45.34 41.78,47.37 41.02,48.13 37.8,48.13 36.45,49.48 36.45,51.69 P8.16
GPIO1_15: length 19.9
  TOP w0.121: P8.15 37.47,49.07 38.03,48.51 41.15,48.51 42.04,47.62 42.04,45.59 43.43,44.2 43.43,41.78 42.8,41.15 42.8,39.12 43.18,38.73 43.18,36.7 43.32,36.56 43.32,35.78 43.32,35.61 U5.U13
GPIO1_16: length 55
  LYR4 w0.133: v1(42.29,43.05) 42.04,43.31 39.24,43.31 36.2,40.26 36.2,39.75 33.53,37.08 33.53,24.08 31.24,21.79 31.24,19.46 31.75,18.95 31.75,7.37 31.24,6.86 31.24,4.06 32.26,3.05 36.32,3.05 P9.15
  BOTTOM w0.133: v1(42.29,43.05) 42.42,42.93 R160.2 R161.2
GPIO1_17: length 53.4
  TOP w0.121: U5.V14 42.12,37.92 41.45,38.58 v1(41.4,38.58)
  LYR4 w0.133: v1(35.31,6.48) 35.31,8.81 36.47,9.98 36.47,18.49 35.66,19.3 35.66,22.96 35.81,23.11 35.81,25.68 36.3,26.16 36.3,26.97 37.7,28.37 37.7,33.56 40.69,36.55 40.69,37.91 41.36,38.58 v1(41.4,38.58)
  BOTTOM w0.121: v1(35.31,6.48) 36.2,5.59 45.59,5.59 46.35,4.83 46.35,3.17 P9.23
GPIO1_28: length 38.6
  TOP w0.121: U5.U18 38.65,35.21 37.76,36.1 37.76,36.14 37.57,36.33 37.57,36.78 37.01,37.34 v1(37.01,37.34)
  LYR4 w0.133: v1(37.01,37.34) 36.96,37.34 36.53,36.91 36.53,36.63 36.31,36.41 35.14,36.41 34.29,35.56 34.29,23.5 34.04,23.24 34.04,17.78 32.66,16.41 32.66,5.87 32.38,5.59 P9.12
GPIO1_29: length 18
  TOP w0.121: U5.V6 48.52,38.73 48.01,39.24 48.01,43.69 49.4,45.09 49.4,49.15 49.15,49.4 49.15,51.69 P8.26
GPIO2_1: length 20.3
  TOP w0.121: U5.V12 43.72,36.67 43.43,36.96 43.43,40.01 43.94,40.51 43.94,44.2 43.05,45.09 43.05,47.12 41.22,48.95 39.75,48.95 39.01,49.68 39.01,51.71 P8.18
GPIO3_18: length 5.9
  TOP w0.121: U5.B12 43.32,22.81 43.32,22.23 42.6,21.52 42.09,21.52 40.77,20.19 v1(40.01,20.19)
  BOTTOM w0.121: v1(40.01,20.19) R51.2
GPIO3_19: length 28.2
  TOP w0.121: v1(42.52,23.61) U5.C13
  LYR4 w0.133: P9.27 51.56,3.05 49.53,3.05 48.77,3.81 48.77,4.93 46.48,7.21 46.48,9.09 45.19,10.39 45.19,11.73 42.93,14 42.93,16.81 42.38,17.36 42.38,21.15 41.85,21.67 41.85,22.94 v1(42.52,23.61)
GPIO3_20: length 5.9
  TOP w0.121: U5.D13 v1(42.52,25.21)
  BOTTOM w0.121: v1(42.52,25.21) 42.12,24.81 42.12,21.38 42.55,20.95 R20.2
GPIO3_21: length 58.4
  TOP w0.121: P9.25 48.9,3.17 48.9,4.95 48.23,5.61 44.93,5.61 44.2,6.35 41.78,6.35 41.25,6.88 41.25,10.36 40.39,11.23 40.39,15.24 38.99,16.64 38.99,20.07 v1(39.12,20.19) 39.75,20.83 40.74,20.83 42.12,22.21 U5.A14 ; v1(38.55,41.4) 38.35,41.4 37.97,41.78
  LYR3 w0.133: v1(35.05,23.55) 35.05,21.59 35.69,20.95 37.97,20.95 38.73,20.19 v1(39.12,20.19)
  LYR4 w0.133: v1(38.55,41.4) 38.48,41.33 38.48,36.58 38.73,36.32 38.73,35.81 37.34,34.42 35.31,34.42 35.05,34.16 v1(35.05,23.55)
GRN_C: length 2
  BOTTOM w0.381: R132.2 5.21,32.26 4.88,32.59 P5.10
GRNA: length 30
  TOP w0.121: 24.33,27.8 v1(24.45,27.69)
  TOP w0.254: U14.3 24.33,27.8
  BOTTOM w0.254: v1(24.45,27.69) 24.19,27.94 23.62,27.94 23.38,27.7 23.38,27.57 23.11,27.3 20.95,27.3 17.78,24.13 15.11,24.13 12.19,27.05 10.79,27.05 10.16,27.69 10.16,28.07 7.62,30.61 C165.1 C163.1 7.62,31.88 6.1,33.4 6.1,33.72 5.83,34.11 4.76,35.18 4.34,35.18 P5.9
HDMI_INT: length 22.1
  TOP w0.121: R169.1 21.97,38.73 R170.1 24.74,38.71 25.88,37.57 34.54,37.57 34.82,37.85 36.01,37.85 36.03,37.86 36.36,37.86 36.38,37.85 37.11,37.85 37.69,37.26 39.7,37.26 40.12,36.84 40.12,35.61 U5.U16
HDMICLK_DISN: length 5.3
  TOP w0.121: Y4.1 40.34,40.45 39.77,39.87 39.75,39.87 39.5,39.62 v1(39.5,39.5) ; v1(39.65,36.7) 39.72,36.63 U5.V17
  LYR3 w0.133: v1(39.65,36.7) 39.5,36.86 v1(39.5,39.5)
I2C0_SCL: length 27.9
  TOP w0.121: v1(26.92,14.03) 26.72,14.24 U2.28 ; R3.2 26.04,20.45 v1(26.92,19.56) ; v1(40.12,23.61) U5.C16
  LYR4 w0.133: v1(26.92,19.56) 27.56,18.92 27.56,14.67 v1(26.92,14.03)
  BOTTOM w0.121: v1(26.92,19.56) 28.19,19.56 28.98,20.34 28.98,21.74 30.1,22.86 U7.1 31.72,22.86 31.98,22.61 36.17,22.61 37.67,21.1 39.14,21.1 39.72,21.69 39.72,23.21 v1(40.12,23.61)
I2C0_SDA: length 33.2
  TOP w0.121: U2.27 26.48,13.84 v1(26.92,13.4) ; v1(36.07,19.68) 36.07,20.1 37.33,21.36 37.33,21.41 37.34,21.41 37.34,22.23 38.72,23.61 39.32,23.61 U5.C17 ; R4.2 v1(26.99,20.57)
  LYR3 w0.133: v1(36.07,19.68) 34.8,19.68 33.27,21.21 27.62,21.21 v1(26.99,20.57)
  LYR4 w0.133: v1(26.92,13.4) 27.81,14.29 27.81,19.75 v1(26.99,20.57)
  BOTTOM w0.121: U7.3 30.82,20.41 30.48,20.07 29.34,20.07 28.32,19.05 26.67,19.05 26.42,19.3 26.42,20 v1(26.99,20.57)
I2C1_SCL: length 25.2
  TOP w0.121: U5.A16 v1(40.12,22.01)
  TOP w0.133: P9.17 41.15,3.05 41.15,5.59 40.01,6.73 v1(40.01,6.99)
  LYR4 w0.133: v1(40.12,22.01) 40.12,21.86 41.23,20.75 41.23,15.49 41.87,14.85 41.87,14.05 44.25,11.67 44.25,11.06 43.48,10.29 43.31,10.29 v1(40.01,6.99)
I2C1_SDA: length 23.1
  TOP w0.121: U5.B16 v1(40.12,22.81)
  LYR4 w0.133: P9.18 39.6,4.85 39.6,7.15 42.99,10.54 43.4,10.54 44.02,11.16 44.02,11.57 41.64,13.95 41.64,14.76 41,15.4 41,20.55 39.71,21.83 39.71,22.4 v1(40.12,22.81)
I2C2_SCL: length 73.5
  TOP w0.121: J4.1 v1(74.37,21.54) ; U5.D17 39.32,24.41 38.51,24.41 37.47,23.37 v1(36.7,23.37)
  LYR3 w0.133: v1(74.37,21.54) 73.79,20.95 73.79,18.85 68.29,13.36 56.26,13.36 53.31,10.41 47.6,10.41 44.42,13.59 v1(39.73,13.59)
  LYR4 w0.133: P9.19 41.4,3.05 39.42,3.05 38.63,3.84 38.63,12.49 v1(39.73,13.59) 37.47,15.85 37.47,20.35 37.1,20.71 37.1,22.97 v1(36.7,23.37)
I2C2_SDA: length 71.1
  TOP w0.121: U5.D18 38.4,24.81 37.47,23.88 36.83,23.88 v1(36.7,24) ; J4.2 v1(74.3,19.54)
  LYR3 w0.133: v1(39.88,12.83) 40.13,13.08 44.53,13.08 47.43,10.18 53.49,10.18 56.39,13.08 68.35,13.08 74.3,19.03 v1(74.3,19.54)
  LYR4 w0.133: P9.20 41.53,3.43 39.37,3.43 38.86,3.94 38.86,11.81 v1(39.88,12.83) 40.15,13.1 40.15,13.74 39.79,14.1 39.66,14.1 37.74,16.01 37.74,20.52 37.34,20.93 37.34,23.37 v1(36.7,24)
JTAG_EMU0: length 23.6
  TOP w0.121: R23.2 36.06,11.87 34.29,13.64 v1(34.29,14.92) ; v1(41.72,23.61) U5.C14
  LYR3 w0.133: v1(42.42,15.75) 38.61,15.75 38.35,15.49 34.86,15.49 v1(34.29,14.92)
  LYR4 w0.133: v1(42.42,15.75) 41.97,16.19 41.97,21.1 41.96,21.11 41.96,21.18 41.59,21.55 41.59,23.11 41.72,23.24 v1(41.72,23.61)
  BOTTOM w0.121: P2.13 v1(34.29,14.92)
JTAG_EMU1: length 15.3
  TOP w0.121: v1(36.07,14.92) 36.26,15.11 R24.2 ; v1(39.73,15.24) 39.65,15.24 38.59,16.3 38.59,20.3 39.5,21.21 40.77,21.21 41.72,22.16 41.72,22.81 U5.B14
  BOTTOM w0.121: v1(36.07,14.92) P2.14 39.18,14.92 39.5,15.24 v1(39.73,15.24)
JTAG_TCK: length 24.1
  TOP w0.121: v1(41.15,11.94) 40.89,12.19 40.89,15.37 40.39,15.88 40.39,19.3 42.35,21.27 42.73,21.27 43.4,21.94 43.4,21.94 43.72,22.26 U5.A12
  LYR3 w0.133: v1(41.15,11.94) 40.7,12.38 v1(34.29,12.38)
  BOTTOM w0.121: P2.11 34.1,13.65 34.29,13.46 v1(34.29,12.38) P2.9
JTAG_TDI: length 24.1
  TOP w0.121: v1(41.8,11.9) 41.27,12.42 41.27,15.59 40.8,16.06 40.8,19.21 42.51,20.92 42.87,20.92 44.12,22.17 44.12,22.81 U5.B11
  BOTTOM w0.121: v1(41.8,11.9) 41.42,11.52 40.5,11.52 39.46,10.48 36.26,10.48 34.35,8.57 P2.3
JTAG_TDO: length 23.7
  TOP w0.121: v1(41.83,11.23) 42.32,11.71 42.32,12.19 41.66,12.85 41.66,15.81 41.15,16.32 41.15,19.05 42.54,20.44 42.54,20.45 43.56,20.45 44.2,21.08 44.2,21.72 44.52,22.04 U5.A11
  LYR3 w0.133: v1(41.83,11.23) 40.82,11.23 40.18,11.86 35.04,11.86 v1(34.29,11.11)
  BOTTOM w0.121: P2.7 v1(34.29,11.11)
JTAG_TMS: length 28.8
  TOP w0.121: v1(45.09,15.75) 44.64,15.3 44.64,9.33 v1(44.2,8.89) ; U5.C11 v1(44.12,23.61)
  LYR4 w0.133: v1(45.09,15.75) 44.39,16.45 44.39,21.6 44.12,21.87 v1(44.12,23.61)
  BOTTOM w0.121: P2.1 34.86,7.3 35.5,7.94 40.2,7.94 41.66,9.4 43.69,9.4 v1(44.2,8.89)
JTAG_TRSTN: length 25.6
  TOP w0.121: v1(36.07,7.3) 36.64,7.3 36.83,7.49 R25.1 ; U5.B10 44.92,22.81 44.92,22.06 44.45,21.59 44.45,20.95 43.69,20.19 42.67,20.19 41.4,18.92 41.4,16.51 41.91,16 41.91,13.08 42.57,12.42 42.57,8.92 v1(42.55,8.89)
  BOTTOM w0.121: v1(42.55,8.89) 41.66,8.89 40.26,7.49 39.12,7.49 38.93,7.3 P2.2 v1(36.07,7.3)
LCD_DATA0: length 33.1
  TOP w0.121: v1(57.89,35.53) 57.25,34.9 53.92,34.9 52.63,33.61 U5.R1 ; R95.1 v1(75.95,48.26)
  LYR3 w0.133: v1(57.89,35.53) 62.45,40.1 66.83,40.1 70.27,43.54 70.71,43.54 73.91,46.74 74.42,46.74 v1(75.95,48.26)
  BOTTOM w0.121: P8.45 75.56,48.64 v1(75.95,48.26) R95.1
LCD_DATA1: length 35.7
  TOP w0.121: R94.1 v1(74.17,48.39) ; v1(57.15,35.56) 55.37,35.56 55.07,35.26 53.92,35.26 52.92,34.25 52.92,34.25 52.68,34.01 52.68,34.01 52.11,34.01 51.72,33.62 U5.R2
  LYR3 w0.133: v1(74.17,48.39) 74.17,47.56 71.41,44.8 71.2,44.8 66.92,40.52 62.11,40.52 v1(57.15,35.56)
  BOTTOM w0.121: P8.46 74.17,51.31 v1(74.17,48.39) R94.1
LCD_DATA2: length 37
  TOP w0.121: v1(73.28,48.39) 73.03,48.64 P8.43 ; v1(73.28,48.39) R93.1 ; v1(73.28,48.39) 73.53,48.39 74.04,48.9 76.07,48.9 76.83,48.13 R75.1 ; v1(51.32,34.01) U5.R3
  LYR3 w0.133: v1(51.32,34.01) 51.44,34.01 51.58,34.16 51.59,34.16 52.44,35 55.96,35 61.85,40.89 66.11,40.89 71.2,45.98 71.2,46.3 v1(73.28,48.39)
  BOTTOM w0.121: R93.1 v1(73.28,48.39)
LCD_DATA3: length 35.6
  TOP w0.121: P8.44 71.93,51.61 71.93,49.16 72.39,48.7 v1(72.39,48.39) R92.1 ; v1(50.52,34.01) U5.R4
  LYR3 w0.133: v1(50.52,34.01) 50.93,34.42 51.49,34.42 52.35,35.28 55.9,35.28 61.77,41.15 66.03,41.15 70.55,45.67 70.55,46.55 v1(72.39,48.39)
  BOTTOM w0.121: R92.1 v1(72.39,48.39)
LCD_DATA4: length 28.1
  TOP w0.121: v1(54.76,35.71) 53.98,35.71 52.67,34.41 U5.T1
  LYR3 w0.133: v1(69.09,44.78) 65.84,41.53 61.72,41.53 55.91,35.71 v1(54.76,35.71)
  BOTTOM w0.121: v1(69.09,44.78) 68.78,45.09 R91.1 68.33,45.09 67.89,45.52 67.89,47.07 68.33,47.5 R66.2 68.38,48.06 P8.41
LCD_DATA5: length 31.1
  TOP w0.121: U5.T2 52.12,34.81 52.69,34.81 54.3,36.42 v1(54.76,36.42)
  LYR3 w0.133: v1(54.76,36.42) 56.24,36.42 61.59,41.78 65.32,41.78 67.21,43.67 67.21,44.08 67.75,44.63 v1(67.79,44.63)
  BOTTOM w0.121: v1(67.79,44.63) 67.59,44.83 67.31,44.83 67.18,44.96 R90.1 67.64,45.54 67.64,47.04 R65.2 67.18,48.39 67.82,49.02 68.33,49.02 69.22,49.91 69.22,51.44 P8.42
LCD_DATA6: length 27.3
  TOP w0.121: U5.T3 51.28,34.77 v1(51.28,34.82)
  LYR3 w0.133: v1(51.28,34.82) 52.2,35.74 53.52,35.74 54.36,36.58 54.36,36.59 54.59,36.83 56.26,36.83 61.59,42.16 64.46,42.16 66.07,43.77 66.07,45.67 v1(65.99,45.75)
  BOTTOM w0.121: R89.1 66.29,45.44 v1(65.99,45.75) 65.79,45.95 65.79,46.99 R64.2 66.29,48.51 P8.39
LCD_DATA7: length 30.3
  TOP w0.121: v1(50.52,34.81) U5.T4
  LYR3 w0.133: v1(50.52,34.81) 51.78,36.07 53.47,36.07 54.55,37.15 56.2,37.15 61.47,42.42 64.14,42.42 64.54,42.82 64.54,43.54 v1(65.66,44.65)
  BOTTOM w0.121: v1(65.66,44.65) 65.23,45.09 R88.1 65.02,45.44 65.53,45.95 65.53,47.12 65.15,47.5 R63.2 65.02,48.26 66.55,49.78 66.55,51.31 P8.40
